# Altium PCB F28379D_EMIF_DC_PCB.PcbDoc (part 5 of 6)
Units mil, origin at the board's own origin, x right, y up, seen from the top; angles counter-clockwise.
Board outline 3000 x 1480 mil, 6 copper layers (Top Layer, Signal Layer 1, Signal Layer 2, Signal Layer 3, Signal Layer 4, Bottom Layer), stack 61.4 mil thick; 51 components, 68 nets, 414 pads, 205 vias.
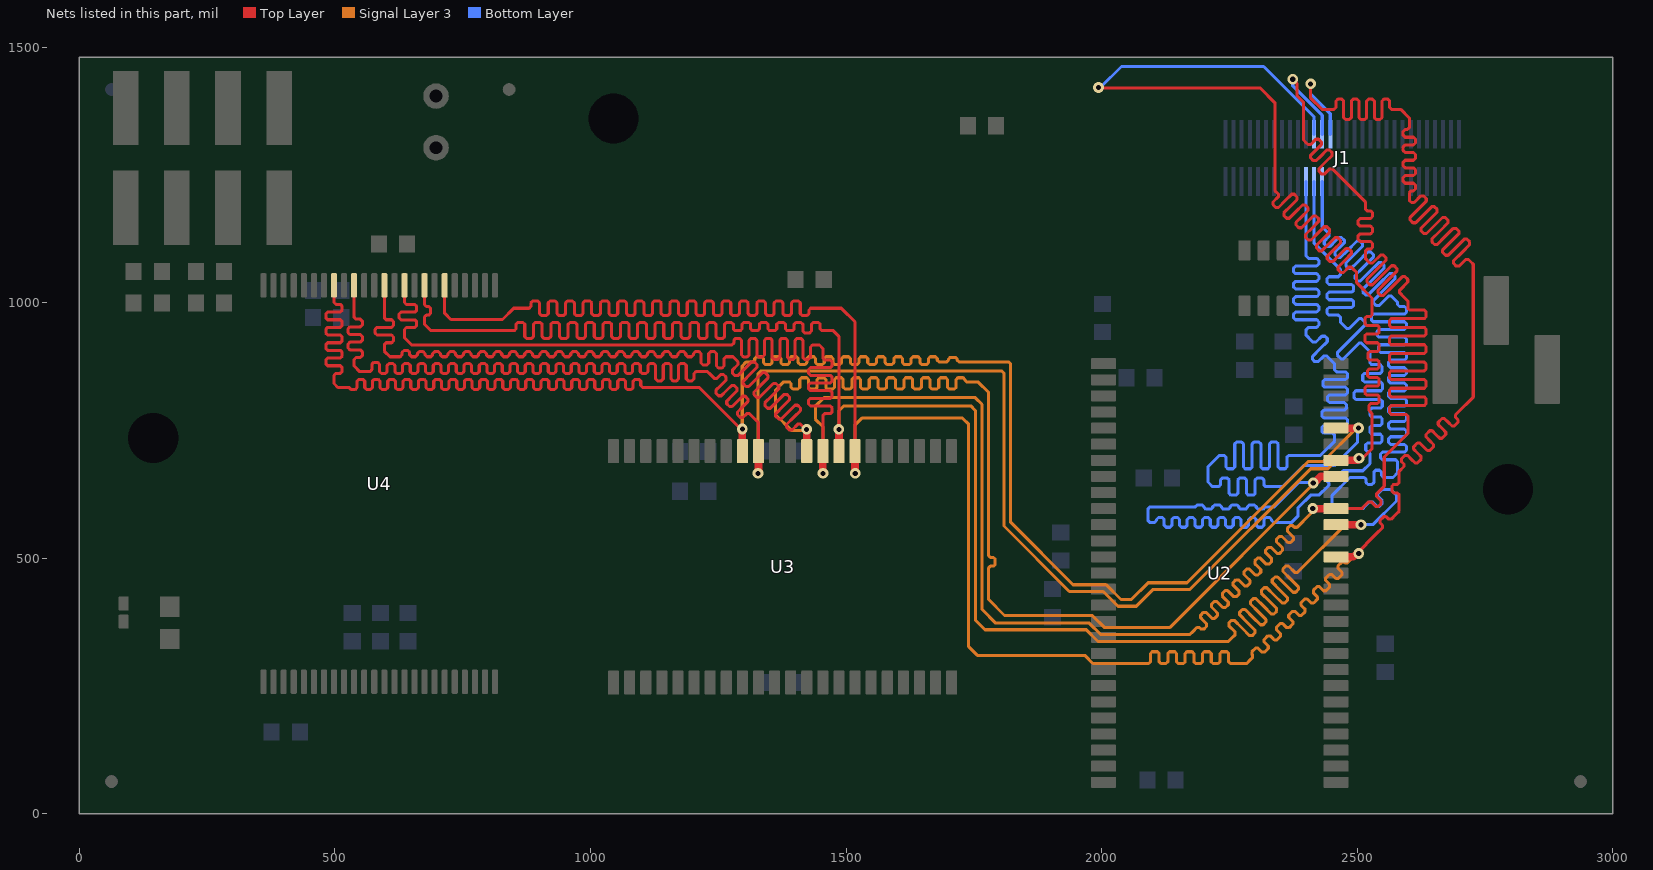
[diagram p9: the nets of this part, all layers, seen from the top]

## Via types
v1: diameter 21, hole 10, Top Layer to Bottom Layer, 204 vias
v2: diameter 20, hole 10, Top Layer to Bottom Layer, 1 vias

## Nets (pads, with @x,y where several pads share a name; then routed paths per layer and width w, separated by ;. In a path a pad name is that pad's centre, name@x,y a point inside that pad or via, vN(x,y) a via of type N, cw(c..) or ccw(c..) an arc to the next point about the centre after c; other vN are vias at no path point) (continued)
EM_D8: J1.34@2447.38,1329.26 U2.42 U3.29 U4.30 | length 6438.6
  Top Layer w6: U4.30@714.95,1033.8 714.95,979 726.95,967 828,967 850,989 875,989 880.1,989 883.5,992.4 883.5,999.59 886.9,1002.99 897.1,1002.99 900.5,999.59 900.5,989 900.5,978.41 903.9,975.01 914.1,975.01 917.5,978.41 917.5,989 917.5,999.59 920.9,1002.99 931.1,1002.99 934.5,999.59 934.5,989 934.5,978.41 937.9,975.01 948.1,975.01 951.5,978.41 951.5,989 951.5,999.59 954.9,1002.99 965.1,1002.99 968.5,999.59 968.5,989 968.5,978.41 971.9,975.01 982.1,975.01 985.5,978.41 985.5,989 985.5,999.59 988.9,1002.99 999.1,1002.99 1002.5,999.59 1002.5,989 1002.5,978.41 1005.9,975.01 1016.1,975.01 1019.5,978.41 1019.5,989 1019.5,999.59 1022.9,1002.99 1033.1,1002.99 1036.5,999.59 1036.5,989 1036.5,978.41 1039.9,975.01 1050.1,975.01 1053.5,978.41 1053.5,989 1053.5,999.59 1056.9,1002.99 1067.1,1002.99 1070.5,999.59 1070.5,989 1070.5,978.41 1073.9,975.01 1084.1,975.01 1087.5,978.41 1087.5,989 1087.5,999.59 1090.9,1002.99 1101.1,1002.99 1104.5,999.59 1104.5,989 1104.5,978.41 1107.9,975.01 1118.1,975.01 1121.5,978.41 1121.5,989 1121.5,999.59 1124.9,1002.99 1135.1,1002.99 1138.5,999.59 1138.5,989 1138.5,978.41 1141.9,975.01 1152.1,975.01 1155.5,978.41 1155.5,989 1155.5,999.59 1158.9,1002.99 1169.1,1002.99 1172.5,999.59 1172.5,989 1172.5,978.41 1175.9,975.01 1186.1,975.01 1189.5,978.41 1189.5,989 1189.5,999.59 1192.9,1002.99 1203.1,1002.99 1206.5,999.59 1206.5,989 1206.5,978.41 1209.9,975.01 1220.1,975.01 1223.5,978.41 1223.5,989 1223.5,999.59 1226.9,1002.99 1237.1,1002.99 1240.5,999.59 1240.5,989 1240.5,978.41 1243.9,975.01 1254.1,975.01 1257.5,978.41 1257.5,989 1257.5,999.59 1260.9,1002.99 1271.1,1002.99 1274.5,999.59 1274.5,989 1274.5,978.41 1277.9,975.01 1288.1,975.01 1291.5,978.41 1291.5,989 1291.5,999.59 1294.9,1002.99 1305.1,1002.99 1308.5,999.59 1308.5,989 1308.5,978.41 1311.9,975.01 1322.1,975.01 1325.5,978.41 1325.5,989 1325.5,999.59 1328.9,1002.99 1339.1,1002.99 1342.5,999.59 1342.5,989 1342.5,978.41 1345.9,975.01 1356.1,975.01 1359.5,978.41 1359.5,989 1359.5,999.59 1362.9,1002.99 1373.1,1002.99 1376.5,999.59 1376.5,989 1376.5,978.41 1379.9,975.01 1390.1,975.01 1393.5,978.41 1393.5,989 1393.5,999.59 1396.9,1002.99 1407.1,1002.99 1410.5,999.59 1410.5,989 1410.5,978.41 1413.9,975.01 1424.1,975.01 1427.5,978.41 1427.5,985.6 1430.9,989 1491,989 1517.73,962.27 U3.29@1517.73,709.38 ; v1(2409,1428) 2409,1400 2431,1378 2451,1378 2454.75,1378 2458.5,1381.75 2458.5,1394.25 2462.25,1398 2469.75,1398 2473.5,1394.25 2473.5,1378 2473.5,1361.75 2477.25,1358 2484.75,1358 2488.5,1361.75 2488.5,1378 2488.5,1394.25 2492.25,1398 2499.75,1398 2503.5,1394.25 2503.5,1378 2503.5,1361.75 2507.25,1358 2514.75,1358 2518.5,1361.75 2518.5,1378 2518.5,1394.25 2522.25,1398 2529.75,1398 2533.5,1394.25 2533.5,1378 2533.5,1361.75 2537.25,1358 2544.75,1358 2548.5,1361.75 2548.5,1378 2548.5,1394.25 2552.25,1398 2559.75,1398 2563.5,1394.25 2563.5,1381.75 2567.25,1378 2578.5,1378 2581,1378 2585,1378 2602,1361 2602,1353.5 2602,1342.25 2598.25,1338.5 2593.75,1338.5 2590,1334.75 2590,1327.25 2593.75,1323.5 2602,1323.5 2610.25,1323.5 2614,1319.75 2614,1312.25 2610.25,1308.5 2602,1308.5 2593.75,1308.5 2590,1304.75 2590,1297.25 2593.75,1293.5 2602,1293.5 2610.25,1293.5 2614,1289.75 2614,1282.25 2610.25,1278.5 2602,1278.5 2593.75,1278.5 2590,1274.75 2590,1267.25 2593.75,1263.5 2602,1263.5 2610.25,1263.5 2614,1259.75 2614,1252.25 2610.25,1248.5 2602,1248.5 2593.75,1248.5 2590,1244.75 2590,1237.25 2593.75,1233.5 2602,1233.5 2610.25,1233.5 2614,1229.75 2614,1222.25 2610.25,1218.5 2605.75,1218.5 2602,1214.75 2602,1203.5 2602,1200 2603.5,1198.5 2606.15,1195.85 2611.45,1195.85 2624.54,1208.93 2629.84,1208.93 2635.14,1203.63 2635.14,1198.32 2619.41,1182.59 2603.68,1166.86 2603.68,1161.55 2608.98,1156.25 2614.28,1156.25 2630.02,1171.98 2645.75,1187.72 2651.05,1187.72 2656.36,1182.41 2656.36,1177.11 2640.62,1161.38 2624.89,1145.64 2624.89,1140.34 2630.19,1135.04 2635.5,1135.04 2651.23,1150.77 2666.96,1166.5 2672.27,1166.5 2677.57,1161.2 2677.57,1155.9 2661.84,1140.16 2646.1,1124.43 2646.1,1119.13 2651.41,1113.82 2656.71,1113.82 2672.44,1129.56 2688.18,1145.29 2693.48,1145.29 2698.78,1139.99 2698.78,1134.68 2683.05,1118.95 2667.32,1103.22 2667.32,1097.91 2672.62,1092.61 2677.92,1092.61 2693.66,1108.34 2709.39,1124.08 2714.69,1124.08 2720,1118.77 2720,1113.47 2704.26,1097.74 2688.53,1082 2688.53,1076.7 2693.83,1071.4 2699.14,1071.4 2712.22,1084.48 2717.52,1084.48 2721.5,1080.5 2727,1075 2727,815 2696,784 2692.39,780.39 2692.39,775.59 2697.34,770.63 2697.34,765.83 2690.13,758.61 2685.32,758.61 2677.97,765.97 2670.61,773.32 2665.81,773.32 2658.59,766.11 2658.59,761.3 2665.95,753.95 2673.3,746.59 2673.3,741.78 2666.09,734.57 2661.28,734.57 2653.93,741.93 2646.57,749.28 2641.76,749.28 2634.55,742.07 2634.55,737.26 2641.91,729.91 2649.26,722.55 2649.26,717.74 2642.05,710.53 2637.24,710.53 2629.89,717.89 2622.53,725.24 2617.72,725.24 2610.51,718.03 2610.51,713.22 2617.86,705.86 2625.22,698.51 2625.22,693.7 2618.01,686.49 2613.2,686.49 2605.84,693.84 2598.49,701.2 2593.68,701.2 2586.47,693.99 2586.47,689.18 2591.42,684.23 2591.42,679.42 2582,670 2582,661.5 2582,647.9 2578.6,644.5 2571.6,644.5 2568.2,641.1 2568.2,630.9 2571.6,627.5 2578.6,627.5 2582,624.1 2582,592 2575.99,585.99 2566.37,576.37 2561.56,576.37 2556.61,581.32 2551.8,581.32 2544.59,574.11 2544.59,569.3 2549.54,564.35 2549.54,559.54 2537.5,547.5 v1@2498,508
  Top Layer w15: U3.29@1517.73,709.38 1517.73,670.27 v1@1518,670 ; U2.42@2459.86,501 U2.42@2458.36,502.5 2492.5,502.5 v1@2498,508
  Signal Layer 3 w6: v1@1518,674 1518,761 1531,774 1728,774 1740,762 1740,327 1757,310 1967,310 1983,294 2091,294 2092.1,294 2095.5,297.4 2095.5,313.6 2098.9,317 2109.1,317 2112.5,313.6 2112.5,297.4 2115.9,294 2126.1,294 2129.5,297.4 2129.5,313.6 2132.9,317 2143.1,317 2146.5,313.6 2146.5,297.4 2149.9,294 2160.1,294 2163.5,297.4 2163.5,313.6 2166.9,317 2177.1,317 2180.5,313.6 2180.5,297.4 2183.9,294 2194.1,294 2197.5,297.4 2197.5,313.6 2200.9,317 2211.1,317 2214.5,313.6 2214.5,297.4 2217.9,294 2228.1,294 2231.5,297.4 2231.5,313.6 2234.9,317 2245.1,317 2248.5,313.6 2248.5,297.4 2251.9,294 2265.5,294 2274,294 2284,294 2292,302 2295.61,305.61 2295.61,310.41 2294.05,311.97 2294.05,316.78 2301.26,323.99 2306.07,323.99 2310.03,320.03 2313.99,316.07 2318.8,316.07 2326.01,323.28 2326.01,328.09 2322.05,332.05 2318.09,336.01 2318.09,340.82 2325.3,348.03 2330.11,348.03 2334.07,344.07 2338.03,340.11 2342.84,340.11 2350.05,347.33 2350.05,352.13 2346.09,356.09 2342.13,360.05 2342.13,364.86 2349.35,372.07 2354.15,372.07 2358.11,368.11 2362.07,364.15 2366.88,364.15 2374.1,371.37 2374.1,376.18 2370.14,380.14 2366.18,384.1 2366.18,388.9 2373.39,396.12 2378.2,396.12 2382.16,392.16 2386.12,388.2 2390.92,388.2 2398.14,395.41 2398.14,400.22 2394.18,404.18 2390.22,408.14 2390.22,412.95 2397.43,420.16 2402.24,420.16 2406.2,416.2 2410.16,412.24 2414.97,412.24 2422.18,419.45 2422.18,424.26 2418.22,428.22 2414.26,432.18 2414.26,436.99 2421.47,444.2 2426.28,444.2 2430.24,440.24 2434.2,436.28 2439.01,436.28 2446.22,443.49 2446.22,448.3 2442.26,452.26 2438.3,456.22 2438.3,461.03 2445.51,468.24 2450.32,468.24 2454.28,464.28 2458.24,460.32 2463.05,460.32 2470.26,467.53 2470.26,472.34 2466.3,476.3 2462.34,480.26 2462.34,485.07 2469.55,492.28 2474.36,492.28 2475.92,490.73 2480.73,490.73 2486,496 v1@2498,508
  Bottom Layer w6: v1(2409,1428) 2409,1408 2447.38,1369.62 J1.34@2447.38,1329.26
  other v1: 2503,509 1518,666
EM_D9: J1.35@2431.63,1236.74 U2.44 U3.30 U4.32 | length 6522.4
  Top Layer w6: U4.32@675.58,1033.8 675.58,1001 675.58,995.9 678.98,992.5 683.84,992.5 687.24,989.1 687.24,978.9 683.84,975.5 678.98,975.5 675.58,972.1 675.58,961 675.58,957.42 688,945 829,945 851.1,945 854.5,948.4 854.5,957.6 857.9,961 868.1,961 871.5,957.6 871.5,945 871.5,933.4 874.9,930 885.1,930 888.5,933.4 888.5,945 888.5,957.6 891.9,961 902.1,961 905.5,957.6 905.5,945 905.5,933.4 908.9,930 919.1,930 922.5,933.4 922.5,945 922.5,957.6 925.9,961 936.1,961 939.5,957.6 939.5,945 939.5,933.4 942.9,930 953.1,930 956.5,933.4 956.5,945 956.5,957.6 959.9,961 970.1,961 973.5,957.6 973.5,945 973.5,933.4 976.9,930 987.1,930 990.5,933.4 990.5,945 990.5,957.6 993.9,961 1004.1,961 1007.5,957.6 1007.5,945 1007.5,933.4 1010.9,930 1021.1,930 1024.5,933.4 1024.5,945 1024.5,957.6 1027.9,961 1038.1,961 1041.5,957.6 1041.5,945 1041.5,933.4 1044.9,930 1055.1,930 1058.5,933.4 1058.5,945 1058.5,957.6 1061.9,961 1072.1,961 1075.5,957.6 1075.5,945 1075.5,933.4 1078.9,930 1089.1,930 1092.5,933.4 1092.5,945 1092.5,957.6 1095.9,961 1106.1,961 1109.5,957.6 1109.5,945 1109.5,933.4 1112.9,930 1123.1,930 1126.5,933.4 1126.5,945 1126.5,957.6 1129.9,961 1140.1,961 1143.5,957.6 1143.5,945 1143.5,933.4 1146.9,930 1157.1,930 1160.5,933.4 1160.5,945 1160.5,957.6 1163.9,961 1174.1,961 1177.5,957.6 1177.5,945 1177.5,933.4 1180.9,930 1191.1,930 1194.5,933.4 1194.5,945 1194.5,957.6 1197.9,961 1208.1,961 1211.5,957.6 1211.5,945 1211.5,933.4 1214.9,930 1225.1,930 1228.5,933.4 1228.5,945 1228.5,957.6 1231.9,961 1242.1,961 1245.5,957.6 1245.5,945 1245.5,933.4 1248.9,930 1259.1,930 1262.5,933.4 1262.5,945 1262.5,957.6 1265.9,961 1276.1,961 1279.5,957.6 1279.5,948.4 1282.9,945 1293.1,945 1296.5,948.4 1296.5,957.6 1299.9,961 1310.1,961 1313.5,957.6 1313.5,948.4 1316.9,945 1327.1,945 1330.5,948.4 1330.5,957.6 1333.9,961 1344.1,961 1347.5,957.6 1347.5,948.4 1350.9,945 1361.1,945 1364.5,948.4 1364.5,957.6 1367.9,961 1378.1,961 1381.5,957.6 1381.5,948.4 1384.9,945 1395.1,945 1398.5,948.4 1398.5,957.6 1401.9,961 1412.1,961 1415.5,957.6 1415.5,945 1415.5,944.26 1418.9,940.86 1429.1,940.86 1432.5,944.26 1432.5,945 1432.5,957.6 1435.9,961 1446.1,961 1449.5,957.6 1449.5,948.4 1452.9,945 1466.5,945 1475,945 1486,934 v1(1486,752) v1@1486,750
  Top Layer w15: v1@1486,745 1486.24,744.76 U3.30@1486.24,709.38 ; U2.44@2458.36,565.49 v1@2506.51,565.49
  Signal Layer 3 w6: v1@1486,745 v1(1486,752) 1486,788 1496,798 1744,798 1753,789 1753,379 1772,360 1970,360 1993,337 2248,337 2253.3,342.3 2261.26,350.26 2261.26,355.56 2248.95,367.87 2248.95,373.18 2254.25,378.48 2259.55,378.48 2274.52,363.52 2289.48,348.55 2294.78,348.55 2300.09,353.86 2300.09,359.16 2285.12,374.12 2270.16,389.09 2270.16,394.39 2275.46,399.69 2280.77,399.69 2295.73,384.73 2310.69,369.77 2316,369.77 2321.3,375.07 2321.3,380.37 2306.34,395.34 2291.37,410.3 2291.37,415.6 2296.67,420.91 2301.98,420.91 2316.94,405.94 2331.91,390.98 2337.21,390.98 2342.51,396.28 2342.51,401.58 2327.55,416.55 2312.58,431.51 2312.58,436.82 2317.89,442.12 2323.19,442.12 2338.16,427.16 2353.12,412.19 2358.42,412.19 2363.73,417.49 2363.73,422.8 2348.76,437.76 2333.8,452.73 2333.8,458.03 2339.1,463.33 2344.4,463.33 2359.37,448.37 2374.33,433.4 2379.64,433.4 2384.94,438.71 2384.94,444.01 2369.98,458.98 2355.01,473.94 2355.01,479.24 2360.31,484.55 2365.62,484.55 2377.93,472.23 2383.23,472.23 2385,474 2476.49,565.49 v1@2506.51,565.49
  Bottom Layer w6: J1.35@2431.63,1236.74 2431.63,1148 2436.93,1142.7 2444.89,1134.74 2444.89,1129.44 2435.57,1120.12 2435.57,1114.81 2440.87,1109.51 2446.17,1109.51 2458.15,1121.48 2464.18,1127.52 2469.48,1127.52 2474.79,1122.21 2474.79,1116.91 2468.75,1110.88 2456.78,1098.9 2456.78,1093.6 2462.08,1088.3 2467.39,1088.3 2479.36,1100.27 2499.7,1120.61 2505.01,1120.61 2510.31,1115.31 2510.31,1110.01 2489.97,1089.66 2477.82,1077.51 2477.82,1072.21 2483.12,1066.91 2488.42,1066.91 2500.57,1079.06 2520.92,1099.4 2526.22,1099.4 2531.52,1094.1 2531.52,1088.79 2511.18,1068.45 2495.58,1052.85 2495.58,1047.55 2500.89,1042.25 2506.19,1042.25 2521.79,1057.84 2542.13,1078.19 2547.43,1078.19 2552.74,1072.88 2552.74,1067.58 2532.39,1047.24 2511,1025.85 2511,1020.54 2516.31,1015.24 2521.61,1015.24 2543,1036.63 2563.34,1056.97 2568.64,1056.97 2573.95,1051.67 2573.95,1046.37 2553.61,1026.02 2532.22,1004.63 2532.22,999.33 2537.52,994.03 2542.82,994.03 2561.56,1012.77 2566.86,1012.77 2574.82,1004.81 2579,1000.63 2579,1000 2579,996.25 2582.75,992.5 2592.63,992.5 2596.38,988.75 2596.38,981.25 2592.63,977.5 2579,977.5 2531.37,977.5 2527.62,973.75 2527.62,966.25 2531.37,962.5 2579,962.5 2592.63,962.5 2596.38,958.75 2596.38,951.25 2592.63,947.5 2579,947.5 2542.56,947.5 2538.81,943.75 2538.81,936.25 2542.56,932.5 2579,932.5 2592.63,932.5 2596.38,928.75 2596.38,921.25 2592.63,917.5 2579,917.5 2545.5,917.5 2541.75,913.75 2541.75,906.25 2545.5,902.5 2579,902.5 2592.63,902.5 2596.38,898.75 2596.38,891.25 2592.63,887.5 2579,887.5 2565.37,887.5 2561.62,883.75 2561.62,876.25 2565.37,872.5 2579,872.5 2592.63,872.5 2596.38,868.75 2596.38,861.25 2592.63,857.5 2579,857.5 2565.37,857.5 2561.62,853.75 2561.62,846.25 2565.37,842.5 2579,842.5 2592.63,842.5 2596.38,838.75 2596.38,831.25 2592.63,827.5 2579,827.5 2565.37,827.5 2561.62,823.75 2561.62,816.25 2565.37,812.5 2579,812.5 2592.63,812.5 2596.38,808.75 2596.38,801.25 2592.63,797.5 2579,797.5 2565.37,797.5 2561.62,793.75 2561.62,786.25 2565.37,782.5 2579,782.5 2592.63,782.5 2596.38,778.75 2596.38,771.25 2592.63,767.5 2579,767.5 2565.37,767.5 2561.62,763.75 2561.62,756.25 2565.37,752.5 2579,752.5 2592.63,752.5 2596.38,748.75 2596.38,741.25 2592.63,737.5 2579,737.5 2565.37,737.5 2561.62,733.75 2561.62,726.25 2565.37,722.5 2579,722.5 2592.63,722.5 2596.38,718.75 2596.38,711.25 2592.63,707.5 2579,707.5 2549.37,707.5 2545.62,703.75 2545.62,696.25 2549.37,692.5 2575.25,692.5 2579,688.75 2579,677.5 2579,667 2570,658 2562.5,658 2551.25,658 2547.5,661.75 2547.5,668.25 2543.75,672 2536.25,672 2532.5,668.25 2532.5,658 2532.5,647.75 2528.75,644 2521.25,644 2517.5,647.75 2517.5,654.25 2513.75,658 2504,658 2486,658 2451,623 2451,602 2456,597 2511,597 2516.3,602.3 2524.26,610.26 2529.56,610.26 2538.3,601.52 2543.61,601.52 2548.91,606.82 2548.91,612.12 2540.17,620.86 2540.17,626.17 2548,634 2566,634 2577,623 2577,612 2530.49,565.49 v1(2507.51,565.49) v1@2506.51,565.49
EM_D10: J1.36@2431.63,1329.26 U2.45 U3.31 U4.34 | length 6440.2
  Top Layer w6: U4.34@636.21,1033.8 636.21,1026.3 636.21,1011.3 636.21,1000.05 639.96,996.3 656.46,996.3 660.21,992.55 660.21,985.05 656.46,981.3 636.21,981.3 629.35,981.3 625.6,977.55 625.6,970.05 629.35,966.3 636.21,966.3 656.46,966.3 660.21,962.55 660.21,955.05 656.46,951.3 639.96,951.3 636.21,947.55 636.21,936.3 636.21,931 650.21,917 1273,917 1276.75,917 1280.5,920.75 1280.5,926.25 1284.25,930 1291.75,930 1295.5,926.25 1295.5,917 1295.5,897.59 1299.25,893.84 1306.75,893.84 1310.5,897.59 1310.5,917 1310.5,926.25 1314.25,930 1321.75,930 1325.5,926.25 1325.5,917 1325.5,897.6 1329.25,893.85 1336.75,893.85 1340.5,897.6 1340.5,917 1340.5,926.25 1344.25,930 1351.75,930 1355.5,926.25 1355.5,917 1355.5,892.75 1359.25,889 1366.75,889 1370.5,892.75 1370.5,917 1370.5,926.25 1374.25,930 1381.75,930 1385.5,926.25 1385.5,917 1385.5,892.75 1389.25,889 1396.75,889 1400.5,892.75 1400.5,917 1400.5,926.25 1404.25,930 1411.75,930 1415.5,926.25 1415.5,917 1415.5,892.75 1419.25,889 1426.75,889 1430.5,892.75 1430.5,913.25 1434.25,917 1445.5,917 1448,917 1454.74,910.26 1454.74,902.76 1454.74,891.51 1458.49,887.76 1469.25,887.76 1473,884.01 1473,876.51 1469.25,872.76 1454.74,872.76 1430.49,872.76 1426.74,869.01 1426.74,861.51 1430.49,857.76 1454.74,857.76 1469.25,857.76 1473,854.01 1473,846.51 1469.25,842.76 1454.74,842.76 1430.49,842.76 1426.74,839.01 1426.74,831.51 1430.49,827.76 1454.74,827.76 1469.25,827.76 1473,824.01 1473,816.51 1469.25,812.76 1454.74,812.76 1430.49,812.76 1426.74,809.01 1426.74,801.51 1430.49,797.76 1454.74,797.76 1469.25,797.76 1473,794.01 1473,786.51 1469.25,782.76 1458.49,782.76 1454.74,779.01 1454.74,754 U3.31@1454.74,709.38 ; v1(2374,1437) 2382,1429 2382,1405 2395,1392 2395,1318 2401,1312 2403.65,1309.35 2408.95,1309.35 2419.21,1319.6 2424.51,1319.6 2429.81,1314.3 2429.81,1308.99 2416.91,1296.09 2409,1288.18 2409,1282.88 2414.3,1277.57 2419.6,1277.57 2427.52,1285.48 2440.42,1298.39 2445.72,1298.39 2451.03,1293.08 2451.03,1287.78 2438.12,1274.88 2425.22,1261.97 2425.22,1256.67 2430.52,1251.37 2435.82,1251.37 2446.08,1261.62 2451.38,1261.62 2495,1218 2516,1197 2516,1187 2516,1183.25 2519.75,1179.5 2526.25,1179.5 2530,1175.75 2530,1168.25 2526.25,1164.5 2516,1164.5 2505.75,1164.5 2502,1160.75 2502,1153.25 2505.75,1149.5 2516,1149.5 2526.25,1149.5 2530,1145.75 2530,1138.25 2526.25,1134.5 2516,1134.5 2505.75,1134.5 2502,1130.75 2502,1123.25 2505.75,1119.5 2516,1119.5 2526.25,1119.5 2530,1115.75 2530,1108.25 2526.25,1104.5 2519.75,1104.5 2516,1100.75 2516,1089.5 2516,1086 2516.5,1085.5 2522,1080 2524.65,1077.35 2529.95,1077.35 2545.86,1093.26 2551.17,1093.26 2556.47,1087.95 2556.47,1082.65 2537.91,1064.09 2519.35,1045.53 2519.35,1040.23 2524.65,1034.92 2529.95,1034.92 2548.52,1053.48 2567.08,1072.05 2572.38,1072.05 2577.68,1066.74 2577.68,1061.44 2559.12,1042.88 2540.56,1024.32 2540.56,1019.01 2545.86,1013.71 2551.17,1013.71 2569.73,1032.27 2588.29,1050.83 2593.59,1050.83 2598.9,1045.53 2598.9,1040.23 2582.99,1024.32 2582.99,1019.01 2590.94,1011.06 2593.5,1008.5 2599,1003 2599,994 2599,988.9 2602.4,985.5 2631.35,985.5 2634.75,982.1 2634.75,971.9 2631.35,968.5 2599,968.5 2566.65,968.5 2563.25,965.1 2563.25,954.9 2566.65,951.5 2599,951.5 2631.35,951.5 2634.75,948.1 2634.75,937.9 2631.35,934.5 2599,934.5 2566.65,934.5 2563.25,931.1 2563.25,920.9 2566.65,917.5 2599,917.5 2631.35,917.5 2634.75,914.1 2634.75,903.9 2631.35,900.5 2599,900.5 2566.65,900.5 2563.25,897.1 2563.25,886.9 2566.65,883.5 2599,883.5 2631.35,883.5 2634.75,880.1 2634.75,869.9 2631.35,866.5 2599,866.5 2566.65,866.5 2563.25,863.1 2563.25,852.9 2566.65,849.5 2599,849.5 2631.35,849.5 2634.75,846.1 2634.75,835.9 2631.35,832.5 2599,832.5 2566.65,832.5 2563.25,829.1 2563.25,818.9 2566.65,815.5 2599,815.5 2631.35,815.5 2634.75,812.1 2634.75,801.9 2631.35,798.5 2599,798.5 2566.65,798.5 2563.25,795.1 2563.25,784.9 2566.65,781.5 2595.6,781.5 2599,778.1 2599,744 2553,698 2553,643 2553,641 2538.15,626.15 2538.15,620.85 2546.99,612.01 2546.99,606.71 2541.69,601.4 2536.38,601.4 2527.55,610.24 2522.24,610.24 2514.29,602.29 2508.98,596.98 U2.45@2458.36,596.98
  Top Layer w15: U3.31@1454.74,709.38 1454.74,670.26 v1@1455,670 ; v1@2419.02,596.98 U2.45@2458.36,596.98
  Signal Layer 3 w6: v1@1455,674 1455,757 1440,772 1440,797 1457,814 1753,814 1766,801 1766,400 1793,373 1976,373 1998,351 2173,351 2178.3,356.3 2186.26,364.26 2191.56,364.26 2194.74,361.08 2200.05,361.08 2205.35,366.38 2205.35,371.68 2199.52,377.52 2193.68,383.35 2193.68,388.65 2198.99,393.96 2204.29,393.96 2210.12,388.12 2215.96,382.29 2221.26,382.29 2226.56,387.59 2226.56,392.9 2220.73,398.73 2214.9,404.56 2214.9,409.87 2220.2,415.17 2225.5,415.17 2231.34,409.34 2237.17,403.5 2242.47,403.5 2247.78,408.81 2247.78,414.11 2241.94,419.94 2236.11,425.78 2236.11,431.08 2241.41,436.38 2246.72,436.38 2252.55,430.55 2258.38,424.72 2263.69,424.72 2268.99,430.02 2268.99,435.32 2263.16,441.16 2257.32,446.99 2257.32,452.29 2262.63,457.6 2267.93,457.6 2273.76,451.76 2279.6,445.93 2284.9,445.93 2290.2,451.23 2290.2,456.54 2284.37,462.37 2278.54,468.2 2278.54,473.51 2283.84,478.81 2289.14,478.81 2294.98,472.98 2300.81,467.14 2306.11,467.14 2311.42,472.45 2311.42,477.75 2305.58,483.58 2299.75,489.42 2299.75,494.72 2305.05,500.02 2310.36,500.02 2316.19,494.19 2322.02,488.36 2327.33,488.36 2332.63,493.66 2332.63,498.96 2326.8,504.8 2320.96,510.63 2320.96,515.93 2326.27,521.24 2331.57,521.24 2337.4,515.4 2343.24,509.57 2348.54,509.57 2353.84,514.87 2353.84,520.18 2348.01,526.01 2342.18,531.84 2342.18,537.15 2347.48,542.45 2352.78,542.45 2358.62,536.62 2364.45,530.78 2369.75,530.78 2375.06,536.09 2375.06,541.39 2369.22,547.22 2363.39,553.06 2363.39,558.36 2368.69,563.66 2374,563.66 2377.18,560.48 2382.48,560.48 2406.5,584.5 v1@2419,597
  Bottom Layer w6: v1(2374,1437) 2374,1424 2431.63,1366.37 J1.36@2431.63,1329.26
  other v1: 2413,597 1455,666
EM_D11: J1.37@2415.88,1236.74 U2.47 U3.32 U4.36 | length 6500.2
  Top Layer w6: U4.36@596.84,1033.8 596.84,974 596.84,970.25 600.59,966.5 611.09,966.5 614.84,962.75 614.84,955.25 611.09,951.5 596.84,951.5 582.59,951.5 578.84,947.75 578.84,940.25 582.59,936.5 596.84,936.5 611.09,936.5 614.84,932.75 614.84,925.25 611.09,921.5 600.59,921.5 596.84,917.75 596.84,907 596.84,905 607.84,894 624,894 627.75,894 631.5,897.75 631.5,902.61 635.25,906.36 642.75,906.36 646.5,902.61 646.5,897.75 650.25,894 657.75,894 661.5,897.75 661.5,900.25 665.25,904 672.75,904 676.5,900.25 676.5,897.75 680.25,894 687.75,894 691.5,897.75 691.5,900.25 695.25,904 702.75,904 706.5,900.25 706.5,897.75 710.25,894 717.75,894 721.5,897.75 721.5,900.25 725.25,904 732.75,904 736.5,900.25 736.5,897.75 740.25,894 747.75,894 751.5,897.75 751.5,900.25 755.25,904 762.75,904 766.5,900.25 766.5,897.75 770.25,894 777.75,894 781.5,897.75 781.5,900.25 785.25,904 792.75,904 796.5,900.25 796.5,897.75 800.25,894 807.75,894 811.5,897.75 811.5,900.25 815.25,904 822.75,904 826.5,900.25 826.5,897.75 830.25,894 837.75,894 841.5,897.75 841.5,900.25 845.25,904 852.75,904 856.5,900.25 856.5,897.75 860.25,894 867.75,894 871.5,897.75 871.5,900.25 875.25,904 882.75,904 886.5,900.25 886.5,897.75 890.25,894 897.75,894 901.5,897.75 901.5,900.25 905.25,904 912.75,904 916.5,900.25 916.5,897.75 920.25,894 927.75,894 931.5,897.75 931.5,900.25 935.25,904 942.75,904 946.5,900.25 946.5,897.75 950.25,894 957.75,894 961.5,897.75 961.5,900.25 965.25,904 972.75,904 976.5,900.25 976.5,897.75 980.25,894 987.75,894 991.5,897.75 991.5,900.25 995.25,904 1002.75,904 1006.5,900.25 1006.5,897.75 1010.25,894 1017.75,894 1021.5,897.75 1021.5,900.25 1025.25,904 1032.75,904 1036.5,900.25 1036.5,897.75 1040.25,894 1047.75,894 1051.5,897.75 1051.5,900.25 1055.25,904 1062.75,904 1066.5,900.25 1066.5,897.75 1070.25,894 1077.75,894 1081.5,897.75 1081.5,900.25 1085.25,904 1092.75,904 1096.5,900.25 1096.5,897.75 1100.25,894 1107.75,894 1111.5,897.75 1111.5,900.25 1115.25,904 1122.75,904 1126.5,900.25 1126.5,897.75 1130.25,894 1137.75,894 1141.5,897.75 1141.5,900.25 1145.25,904 1152.75,904 1156.5,900.25 1156.5,897.75 1160.25,894 1167.75,894 1171.5,897.75 1171.5,900.25 1175.25,904 1182.75,904 1186.5,900.25 1186.5,897.75 1190.25,894 1197.75,894 1201.5,897.75 1201.5,900.25 1205.25,904 1212.75,904 1216.5,900.25 1216.5,894 1216.5,881.75 1220.25,878 1227.75,878 1231.5,881.75 1231.5,894 1231.5,900.25 1235.25,904 1242.75,904 1246.5,900.25 1246.5,894 1246.5,875.91 1250.25,872.16 1257.75,872.16 1261.5,875.91 1261.5,890.25 1265.25,894 1270,894 1279,894 1280,893 1288.87,884.13 1288.87,878.82 1277.64,867.59 1277.64,862.29 1282.94,856.98 1288.24,856.98 1302.13,870.87 1315.36,884.09 1320.66,884.09 1325.96,878.79 1325.96,873.49 1312.74,860.26 1298.85,846.38 1298.85,841.07 1304.15,835.77 1309.46,835.77 1323.34,849.66 1336.57,862.88 1341.87,862.88 1347.18,857.58 1347.18,852.27 1333.95,839.05 1320.06,825.16 1320.06,819.86 1325.37,814.56 1330.67,814.56 1344.56,828.44 1357.78,841.67 1363.09,841.67 1368.39,836.36 1368.39,831.06 1355.16,817.84 1341.28,803.95 1341.28,798.65 1346.58,793.34 1351.88,793.34 1365.77,807.23 1379,820.45 1384.3,820.45 1389.6,815.15 1389.6,809.85 1376.38,796.62 1362.49,782.74 1362.49,777.43 1367.79,772.13 1373.1,772.13 1386.98,786.02 1400.21,799.24 1405.51,799.24 1410.82,793.94 1410.82,788.64 1397.59,775.41 1383.7,761.52 1383.7,756.22 1389.01,750.92 1394.31,750.92 1405.55,762.15 1410.85,762.15 1413.5,759.5 v1@1423,750
  Top Layer w15: v1@1423,745 1423.24,744.76 U3.32@1423.24,709.38 ; v1@2417.02,647.98 2429.02,659.98 U2.47@2458.36,659.98
  Signal Layer 3 w6: v1@1423,745 1423,750 1393,750 1362,781 1362,829 1378,845 1389.1,845 1392.5,841.6 1392.5,834.4 1395.9,831 1406.1,831 1409.5,834.4 1409.5,845 1409.5,849.6 1412.9,853 1423.1,853 1426.5,849.6 1426.5,845 1426.5,834.4 1429.9,831 1440.1,831 1443.5,834.4 1443.5,845 1443.5,849.6 1446.9,853 1457.1,853 1460.5,849.6 1460.5,845 1460.5,834.4 1463.9,831 1474.1,831 1477.5,834.4 1477.5,845 1477.5,849.6 1480.9,853 1491.1,853 1494.5,849.6 1494.5,845 1494.5,834.4 1497.9,831 1508.1,831 1511.5,834.4 1511.5,845 1511.5,849.6 1514.9,853 1525.1,853 1528.5,849.6 1528.5,845 1528.5,834.4 1531.9,831 1542.1,831 1545.5,834.4 1545.5,845 1545.5,849.6 1548.9,853 1559.1,853 1562.5,849.6 1562.5,845 1562.5,834.4 1565.9,831 1576.1,831 1579.5,834.4 1579.5,845 1579.5,849.6 1582.9,853 1593.1,853 1596.5,849.6 1596.5,845 1596.5,834.4 1599.9,831 1610.1,831 1613.5,834.4 1613.5,845 1613.5,849.6 1616.9,853 1627.1,853 1630.5,849.6 1630.5,845 1630.5,834.4 1633.9,831 1644.1,831 1647.5,834.4 1647.5,845 1647.5,849.6 1650.9,853 1661.1,853 1664.5,849.6 1664.5,845 1664.5,834.4 1667.9,831 1678.1,831 1681.5,834.4 1681.5,845 1681.5,849.6 1684.9,853 1695.1,853 1698.5,849.6 1698.5,845 1698.5,834.4 1701.9,831 1712.1,831 1715.5,834.4 1715.5,845 1715.5,849.6 1718.9,853 1729.1,853 1732.5,849.6 1732.5,848.4 1735.9,845 1749.5,845 1758,845 1779,824 1779,510 1779,504.9 1782.4,501.5 1788.4,501.5 1791.8,498.1 1791.8,487.9 1788.4,484.5 1782.4,484.5 1779,481.1 1779,473 1779,419 1810,388 1982,388 2006,364 2133.05,364 v1@2417.02,647.98
  Bottom Layer w6: J1.37@2415.88,1236.74 2415.88,1116.12 2467,1065 2467,1054.25 2463.25,1050.5 2444.75,1050.5 2441,1046.75 2441,1039.25 2444.75,1035.5 2467,1035.5 2489.25,1035.5 2493,1031.75 2493,1024.25 2489.25,1020.5 2467,1020.5 2444.75,1020.5 2441,1016.75 2441,1009.25 2444.75,1005.5 2467,1005.5 2489.25,1005.5 2493,1001.75 2493,994.25 2489.25,990.5 2467,990.5 2444.75,990.5 2441,986.75 2441,979.25 2444.75,975.5 2463.25,975.5 2467,971.75 2467,962 2476,953 2479.61,949.39 2484.41,949.39 2503.57,968.55 2508.38,968.55 2515.59,961.34 2515.59,956.53 2494.03,934.97 2461.08,902.02 2461.08,897.21 2468.29,890 2473.1,890 2504.1,921 2508,921 2525,904 2525,887 2525,881.9 2528.4,878.5 2545.27,878.5 2548.67,875.1 2548.67,864.9 2545.27,861.5 2525,861.5 2514.35,861.5 2510.95,858.1 2510.95,847.9 2514.35,844.5 2525,844.5 2546.29,844.5 2549.69,841.1 2549.69,830.9 2546.29,827.5 2525,827.5 2497.47,827.5 2494.07,824.1 2494.07,813.9 2497.47,810.5 2525,810.5 2545.61,810.5 2549.01,807.1 2549.01,796.9 2545.61,793.5 2528.4,793.5 2525,790.1 2525,779.9 2528.4,776.5 2545.22,776.5 2548.62,773.1 2548.62,762.9 2545.22,759.5 2528.4,759.5 2525,756.1 2525,745.9 2528.4,742.5 2545.22,742.5 2548.62,739.1 2548.62,728.9 2545.22,725.5 2525,725.5 2520.2,725.5 2516.8,722.1 2516.8,711.9 2520.2,708.5 2521.6,708.5 2525,705.1 2525,704 2525,685 2511,671 2473,671 2466.5,664.5 2461.44,659.44 2456.63,659.44 2448.06,668 2443.25,668 2436.04,660.79 2436.04,655.98 2444.61,647.41 2444.61,642.61 2441,639 2426,624 2410,624 2384,598 2384,582 2372,570 2350,570 2336.25,570 2332.5,573.75 2332.5,575.75 2328.75,579.5 2321.25,579.5 2317.5,575.75 2317.5,570 2317.5,564.25 2313.75,560.5 2306.25,560.5 2302.5,564.25 2302.5,570 2302.5,575.75 2298.75,579.5 2291.25,579.5 2287.5,575.75 2287.5,570 2287.5,564.25 2283.75,560.5 2276.25,560.5 2272.5,564.25 2272.5,570 2272.5,575.75 2268.75,579.5 2261.25,579.5 2257.5,575.75 2257.5,570 2257.5,564.25 2253.75,560.5 2246.25,560.5 2242.5,564.25 2242.5,570 2242.5,575.75 2238.75,579.5 2231.25,579.5 2227.5,575.75 2227.5,570 2227.5,564.25 2223.75,560.5 2216.25,560.5 2212.5,564.25 2212.5,570 2212.5,575.75 2208.75,579.5 2201.25,579.5 2197.5,575.75 2197.5,570 2197.5,564.25 2193.75,560.5 2186.25,560.5 2182.5,564.25 2182.5,570 2182.5,575.75 2178.75,579.5 2171.25,579.5 2167.5,575.75 2167.5,570 2167.5,564.25 2163.75,560.5 2156.25,560.5 2152.5,564.25 2152.5,570 2152.5,575.75 2148.75,579.5 2141.25,579.5 2137.5,575.75 2137.5,570 2137.5,564.25 2133.75,560.5 2126.25,560.5 2122.5,564.25 2122.5,570 2122.5,575.75 2118.75,579.5 2111.25,579.5 2107.5,575.75 2107.5,573.75 2103.75,570 2100,570 2094,570 2091,573 2091,597 2094,600 2175,600 2182.9,600 2183.5,600.6 2186.9,604 2197.1,604 2200.5,600.6 2200.5,600 2200.5,599.4 2203.9,596 2214.1,596 2217.5,599.4 2217.5,600 2217.5,600.6 2220.9,604 2231.1,604 2234.5,600.6 2234.5,600 2234.5,599.4 2237.9,596 2248.1,596 2251.5,599.4 2251.5,600 2251.5,600.6 2254.9,604 2265.1,604 2268.5,600.6 2268.5,600 2268.5,599.4 2271.9,596 2282.1,596 2285.5,599.4 2285.5,600 2285.5,600.6 2288.9,604 2299.1,604 2302.5,600.6 2302.5,600 2302.5,599.4 2305.9,596 2316.1,596 2319.5,599.4 2320.1,600 2333,600 2338,600 2385.98,647.98 v1@2417.02,647.98
  other v1: 2414.02,646.98 1423,752
EM_D12: J1.38@2415.88,1329.26 U2.48 U3.35 U4.39 | length 6413.3
  Top Layer w6: U4.39@537.79,1033.8 537.79,975 537.79,971.25 541.54,967.5 550.04,967.5 553.79,963.75 553.79,956.25 550.04,952.5 537.79,952.5 529.38,952.5 525.63,948.75 525.63,941.25 529.38,937.5 537.79,937.5 550.04,937.5 553.79,933.75 553.79,926.25 550.04,922.5 537.79,922.5 529.38,922.5 525.63,918.75 525.63,911.25 529.38,907.5 537.79,907.5 550.04,907.5 553.79,903.75 553.79,896.25 550.04,892.5 541.54,892.5 537.79,888.75 537.79,886 537.79,876 548.79,865 565,865 568.75,865 572.5,868.75 572.5,879.25 576.25,883 583.75,883 587.5,879.25 587.5,865 ; 587.5,864.96 591.25,861.21 598.75,861.21 602.5,864.96 ; 602.5,865 602.5,877.25 606.25,881 613.75,881 617.5,877.25 617.5,865 ; 617.5,864.96 621.25,861.21 628.75,861.21 632.5,864.96 ; 632.5,865 632.5,877.25 636.25,881 643.75,881 647.5,877.25 647.5,865 ; 647.5,864.96 651.25,861.21 658.75,861.21 662.5,864.96 ; 662.5,865 662.5,877.25 666.25,881 673.75,881 677.5,877.25 677.5,865 ; 677.5,864.96 681.25,861.21 688.75,861.21 692.5,864.96 ; 692.5,865 692.5,877.25 696.25,881 703.75,881 707.5,877.25 707.5,865 ; 707.5,864.96 711.25,861.21 718.75,861.21 722.5,864.96 ; 722.5,865 722.5,877.25 726.25,881 733.75,881 737.5,877.25 737.5,865 ; 737.5,864.96 741.25,861.21 748.75,861.21 752.5,864.96 ; 752.5,865 752.5,877.25 756.25,881 763.75,881 767.5,877.25 767.5,865 ; 767.5,864.96 771.25,861.21 778.75,861.21 782.5,864.96 ; 782.5,865 782.5,877.25 786.25,881 793.75,881 797.5,877.25 797.5,865 ; 797.5,864.96 801.25,861.21 808.75,861.21 812.5,864.96 ; 812.5,865 812.5,877.25 816.25,881 823.75,881 827.5,877.25 827.5,865 ; 827.5,864.96 831.25,861.21 838.75,861.21 842.5,864.96 ; 842.5,865 842.5,877.25 846.25,881 853.75,881 857.5,877.25 857.5,865 ; 857.5,864.96 861.25,861.21 868.75,861.21 872.5,864.96 ; 872.5,865 872.5,877.25 876.25,881 883.75,881 887.5,877.25 887.5,865 ; 887.5,864.96 891.25,861.21 898.75,861.21 902.5,864.96 ; 902.5,865 902.5,877.25 906.25,881 913.75,881 917.5,877.25 917.5,865 ; 917.5,864.96 921.25,861.21 928.75,861.21 932.5,864.96 ; 932.5,865 932.5,877.25 936.25,881 943.75,881 947.5,877.25 947.5,865 ; 947.5,864.96 951.25,861.21 958.75,861.21 962.5,864.96 ; 962.5,865 962.5,877.25 966.25,881 973.75,881 977.5,877.25 977.5,865 ; 977.5,864.96 981.25,861.21 988.75,861.21 992.5,864.96 ; 992.5,865 992.5,877.25 996.25,881 1003.75,881 1007.5,877.25 1007.5,865 ; 1007.5,864.96 1011.25,861.21 1018.75,861.21 1022.5,864.96 ; 1022.5,865 1022.5,877.25 1026.25,881 1033.75,881 1037.5,877.25 1037.5,865 ; 1037.5,864.96 1041.25,861.21 1048.75,861.21 1052.5,864.96 ; 1052.5,865 1052.5,877.25 1056.25,881 1063.75,881 1067.5,877.25 1067.5,865 ; 1067.5,864.96 1071.25,861.21 1078.75,861.21 1082.5,864.96 ; 1082.5,865 1082.5,877.25 1086.25,881 1093.75,881 1097.5,877.25 1097.5,865 ; 1097.5,864.96 1101.25,861.21 1108.75,861.21 1112.5,864.96 ; 1112.5,865 1112.5,877.25 1116.25,881 1123.75,881 1127.5,877.25 1127.5,865 1127.5,850.75 1131.25,847 1138.75,847 1142.5,850.75 1142.5,865 1142.5,877.25 1146.25,881 1153.75,881 1157.5,877.25 1157.5,865 1157.5,850.75 1161.25,847 1168.75,847 1172.5,850.75 1172.5,865 1172.5,877.25 1176.25,881 1183.75,881 1187.5,877.25 1187.5,865 1187.5,850.75 1191.25,847 1198.75,847 1202.5,850.75 1202.5,861.25 1206.25,865 1217.5,865 1229,865 1234.3,859.7 1242.26,851.74 1247.56,851.74 1254.99,859.17 1260.29,859.17 1265.59,853.86 1265.59,848.56 1255.52,838.48 1245.44,828.41 1245.44,823.1 1250.74,817.8 1256.05,817.8 1266.12,827.88 1276.2,837.95 1281.5,837.95 1286.81,832.65 1286.81,827.35 1276.73,817.27 1266.65,807.19 1266.65,801.89 1271.96,796.59 1277.26,796.59 1287.34,806.66 1297.41,816.74 1302.72,816.74 1308.02,811.44 1308.02,806.13 1297.94,796.06 1287.87,785.98 1287.87,780.68 1293.17,775.37 1298.47,775.37 1305.9,782.8 1311.2,782.8 1328.76,765.24 1328.76,757.74 1328.76,753 U3.35@1328.76,709.38 ; v1@1994,1420 2310,1420 2339,1391 2339,1219 2344,1214 2345.66,1212.34 2345.66,1207.04 2335.41,1196.78 2335.41,1191.48 2340.71,1186.18 2346.01,1186.18 2358.92,1199.08 2371.82,1211.99 2377.13,1211.99 2382.43,1206.68 2382.43,1201.38 2369.52,1188.48 2356.62,1175.57 2356.62,1170.27 2361.92,1164.96 2367.23,1164.96 2380.13,1177.87 2393.04,1190.77 2398.34,1190.77 2403.64,1185.47 2403.64,1180.17 2390.74,1167.26 2380.48,1157.01 2380.48,1151.71 2385.79,1146.4 2391.09,1146.4 2401.34,1156.66 2414.25,1169.56 2419.55,1169.56 2424.86,1164.26 2424.86,1158.95 2411.95,1146.05 2399.05,1133.14 2399.05,1127.84 2404.35,1122.54 2409.65,1122.54 2422.56,1135.44 2435.46,1148.35 2440.77,1148.35 2446.07,1143.04 2446.07,1137.74 2433.16,1124.84 2420.26,1111.93 2420.26,1106.63 2425.56,1101.32 2430.87,1101.32 2443.77,1114.23 2456.68,1127.13 2461.98,1127.13 2467.28,1121.83 2467.28,1116.53 2454.38,1103.62 2441.47,1090.72 2441.47,1085.42 2446.78,1080.11 2452.08,1080.11 2464.98,1093.02 2477.89,1105.92 2483.19,1105.92 2488.49,1100.62 2488.49,1095.31 2475.59,1082.41 2462.69,1069.51 2462.69,1064.2 2467.99,1058.9 2473.29,1058.9 2483.55,1069.15 2488.85,1069.15 2491.5,1066.5 2499,1059 2499,1039 2529,1009 2529,983 2529,975.9 2525.6,972.5 2518.4,972.5 2515,969.1 2515,958.9 2518.4,955.5 2529,955.5 2539.6,955.5 2543,952.1 2543,941.9 2539.6,938.5 2529,938.5 2518.4,938.5 2515,935.1 2515,924.9 2518.4,921.5 2529,921.5 2539.6,921.5 2543,918.1 2543,907.9 2539.6,904.5 2529,904.5 2524.45,904.5 2521.05,901.1 2521.05,890.9 2524.45,887.5 2529,887.5 2539.6,887.5 2543,884.1 2543,873.9 2539.6,870.5 2529,870.5 2523.83,870.5 2520.43,867.1 2520.43,856.9 2523.83,853.5 2529,853.5 2539.6,853.5 2543,850.1 2543,839.9 2539.6,836.5 2529,836.5 2518.4,836.5 2515,833.1 2515,822.9 2518.4,819.5 2529,819.5 2539.6,819.5 2543,816.1 2543,805.9 2539.6,802.5 2529,802.5 2526.38,802.5 2522.98,799.1 2522.98,788.9 2526.38,785.5 2529,782.88 2529,777 2529,714 2506.47,691.47 v1@2503.53,691.47
  Top Layer w15: v1(1328,666) 1328.76,666.76 U3.35@1328.76,709.38 ; U2.48@2458.36,691.47 2499.53,691.47 v1(2503.53,695.47)
  Signal Layer 3 w6: v1@1328,674 1328,861 1333,866 1805,866 1809,862 1809,563 1937,435 2003,435 2032,406 2068,406 2101,439 2173,439 2409,675 2443,675 2459.47,691.47 v1@2500.53,691.47
  Bottom Layer w6: v1@1994,1417 v1@1998,1421 ; v1(1994,1421) v1@1998,1421 ; J1.38@2415.88,1329.26 2415.88,1363.12 2317,1462 2039,1462 v1@1998,1421
EM_D13: J1.39@2400.13,1236.74 U2.50 U3.36 U4.41 | length 6522.4
  Top Layer w6: U4.41@498.42,1033.8 498.42,1004 498.42,1000.25 502.17,996.5 510.62,996.5 514.37,992.75 514.37,985.25 510.62,981.5 498.42,981.5 486.21,981.5 482.46,977.75 482.46,970.25 486.21,966.5 498.42,966.5 510.62,966.5 514.37,962.75 514.37,955.25 510.62,951.5 498.42,951.5 486.21,951.5 482.46,947.75 482.46,940.25 486.21,936.5 498.42,936.5 510.62,936.5 514.37,932.75 514.37,925.25 510.62,921.5 498.42,921.5 486.21,921.5 482.46,917.75 482.46,910.25 486.21,906.5 498.42,906.5 510.62,906.5 514.37,902.75 514.37,895.25 510.62,891.5 498.42,891.5 486.21,891.5 482.46,887.75 482.46,880.25 486.21,876.5 498.42,876.5 510.62,876.5 514.37,872.75 514.37,865.25 510.62,861.5 502.17,861.5 498.42,857.75 498.42,846.5 498.42,841.58 506,834 513.5,834 528.03,834 528.5,833.53 532.25,829.78 539.75,829.78 543.5,833.53 543.5,834 543.5,846.2 547.25,849.95 554.75,849.95 558.5,846.2 558.5,834 558.5,833.57 562.25,829.82 569.75,829.82 573.5,833.57 573.5,834 573.5,846.2 577.25,849.95 584.75,849.95 588.5,846.2 588.5,834 588.5,833.57 592.25,829.82 599.75,829.82 603.5,833.57 603.5,834 603.5,846.2 607.25,849.95 614.75,849.95 618.5,846.2 618.5,834 618.5,833.57 622.25,829.82 629.75,829.82 633.5,833.57 633.5,834 633.5,846.2 637.25,849.95 644.75,849.95 648.5,846.2 648.5,834 648.5,833.57 652.25,829.82 659.75,829.82 663.5,833.57 663.5,834 663.5,846.2 667.25,849.95 674.75,849.95 678.5,846.2 678.5,834 678.5,833.57 682.25,829.82 689.75,829.82 693.5,833.57 693.5,834 693.5,846.2 697.25,849.95 704.75,849.95 708.5,846.2 708.5,834 708.5,833.57 712.25,829.82 719.75,829.82 723.5,833.57 723.5,834 723.5,846.2 727.25,849.95 734.75,849.95 738.5,846.2 738.5,834 738.5,833.57 742.25,829.82 749.75,829.82 753.5,833.57 753.5,834 753.5,846.2 757.25,849.95 764.75,849.95 768.5,846.2 768.5,834 768.5,833.57 772.25,829.82 779.75,829.82 783.5,833.57 783.5,834 783.5,846.2 787.25,849.95 794.75,849.95 798.5,846.2 798.5,834 798.5,833.57 802.25,829.82 809.75,829.82 813.5,833.57 813.5,834 813.5,846.2 817.25,849.95 824.75,849.95 828.5,846.2 828.5,834 828.5,833.57 832.25,829.82 839.75,829.82 843.5,833.57 843.5,834 843.5,846.2 847.25,849.95 854.75,849.95 858.5,846.2 858.5,834 858.5,833.57 862.25,829.82 869.75,829.82 873.5,833.57 873.5,834 873.5,846.2 877.25,849.95 884.75,849.95 888.5,846.2 888.5,834 888.5,833.57 892.25,829.82 899.75,829.82 903.5,833.57 903.5,834 903.5,846.2 907.25,849.95 914.75,849.95 918.5,846.2 918.5,834 918.5,833.57 922.25,829.82 929.75,829.82 933.5,833.57 933.5,834 933.5,846.2 937.25,849.95 944.75,849.95 948.5,846.2 948.5,834 948.5,833.57 952.25,829.82 959.75,829.82 963.5,833.57 963.5,834 963.5,846.2 967.25,849.95 974.75,849.95 978.5,846.2 978.5,834 978.5,833.57 982.25,829.82 989.75,829.82 993.5,833.57 993.5,834 993.5,846.2 997.25,849.95 1004.75,849.95 1008.5,846.2 1008.5,834 1008.5,833.57 1012.25,829.82 1019.75,829.82 1023.5,833.57 1023.5,834 1023.5,846.2 1027.25,849.95 1034.75,849.95 1038.5,846.2 1038.5,834 1038.5,833.57 1042.25,829.82 1049.75,829.82 1053.5,833.57 1053.5,834 1053.5,846.2 1057.25,849.95 1064.75,849.95 1068.5,846.2 1068.5,834 1068.5,833.57 1072.25,829.82 1079.75,829.82 1083.5,833.57 1083.5,834 1083.5,846.2 1087.25,849.95 1094.75,849.95 1098.5,846.2 1098.5,837.75 1102.25,834 1213,834 v1@1297.26,749.74
  Top Layer w15: U3.36@1297.26,709.38 1297.26,749.74 v1(1297.26,752.74) ; U2.50@2458.36,754.46 v1@2500.54,754.46
  Signal Layer 3 w6: v1@1297,745 1297,876 1305,884 1313,884 1318.1,884 1321.5,887.4 1321.5,890.6 1324.9,894 1335.1,894 1338.5,890.6 1338.5,884 1338.5,882.4 1341.9,879 1352.1,879 1355.5,882.4 1355.5,884 1355.5,890.6 1358.9,894 1369.1,894 1372.5,890.6 1372.5,884 1372.5,882.4 1375.9,879 1386.1,879 1389.5,882.4 1389.5,884 1389.5,890.6 1392.9,894 1403.1,894 1406.5,890.6 1406.5,884 1406.5,882.4 1409.9,879 1420.1,879 1423.5,882.4 1423.5,884 1423.5,890.6 1426.9,894 1437.1,894 1440.5,890.6 1440.5,884 1440.5,882.4 1443.9,879 1454.1,879 1457.5,882.4 1457.5,884 1457.5,890.6 1460.9,894 1471.1,894 1474.5,890.6 1474.5,884 1474.5,882.4 1477.9,879 1488.1,879 1491.5,882.4 1491.5,884 1491.5,890.6 1494.9,894 1505.1,894 1508.5,890.6 1508.5,884 1508.5,882.4 1511.9,879 1522.1,879 1525.5,882.4 1525.5,884 1525.5,890.6 1528.9,894 1539.1,894 1542.5,890.6 1542.5,884 1542.5,882.4 1545.9,879 1556.1,879 1559.5,882.4 1559.5,884 1559.5,890.6 1562.9,894 1573.1,894 1576.5,890.6 1576.5,884 1576.5,882.4 1579.9,879 1590.1,879 1593.5,882.4 1593.5,884 1593.5,890.6 1596.9,894 1607.1,894 1610.5,890.6 1610.5,884 1610.5,882.4 1613.9,879 1624.1,879 1627.5,882.4 1627.5,884 1627.5,890.6 1630.9,894 1641.1,894 1644.5,890.6 1644.5,884 1644.5,882.4 1647.9,879 1658.1,879 1661.5,882.4 1661.5,884 1661.5,890.6 1664.9,894 1675.1,894 1678.5,890.6 1678.5,887.4 1681.9,884 1684,884 1692,884 1697.1,884 1700.5,887.4 1700.5,889.46 1703.9,892.86 1714.1,892.86 1717.5,889.46 1717.5,887.4 1720.9,884 1746,884 1818,884 1822,880 1822,570 1944,448 2009,448 2038,419 2058,419 2091,452 2167,452 2404,689 2433,689 2498.46,754.46 v1@2500.54,754.46
  Bottom Layer w6: J1.39@2400.13,1236.74 2400.13,1094 2400.13,1091 2404.63,1086.5 2420.63,1086.5 2425.13,1082 2425.13,1076 2420.63,1071.5 2400.13,1071.5 2379.63,1071.5 2375.13,1067 2375.13,1061 2379.63,1056.5 2400.13,1056.5 2420.63,1056.5 2425.13,1052 2425.13,1046 2420.63,1041.5 2400.13,1041.5 2379.63,1041.5 2375.13,1037 2375.13,1031 2379.63,1026.5 2400.13,1026.5 2420.63,1026.5 2425.13,1022 2425.13,1016 2420.63,1011.5 2400.13,1011.5 2379.63,1011.5 2375.13,1007 2375.13,1001 2379.63,996.5 2400.13,996.5 2420.63,996.5 2425.13,992 2425.13,986 2420.63,981.5 2400.13,981.5 2379.63,981.5 2375.13,977 2375.13,971 2379.63,966.5 2400.13,966.5 2420.63,966.5 2425.13,962 2425.13,956 2420.63,951.5 2404.63,951.5 2400.13,947 2400.13,938 2400.13,935.87 2411,925 2413.12,922.88 2419.49,922.88 2430.8,934.19 2437.16,934.19 2441.41,929.95 2441.41,923.59 2426.91,909.09 2412.78,894.96 2412.78,888.6 2417.03,884.36 2423.39,884.36 2434.33,895.3 2440.7,895.3 2443.5,892.5 2456,880 2456,872 2456,868.25 2459.75,864.5 2477.33,864.5 2481.08,860.75 2481.08,853.25 2477.33,849.5 2456,849.5 2436.6,849.5 2432.85,845.75 2432.85,838.25 2436.6,834.5 2456,834.5 2477.33,834.5 2481.08,830.75 2481.08,823.25 2477.33,819.5 2456,819.5 2445.67,819.5 2441.92,815.75 2441.92,808.25 2445.67,804.5 2456,804.5 2474.99,804.5 2478.74,800.75 2478.74,793.25 2474.99,789.5 2456,789.5 2434.67,789.5 2430.92,785.75 2430.92,778.25 2434.67,774.5 2456,774.5 2477.33,774.5 2481.08,770.75 2481.08,763.25 2477.33,759.5 2456,759.5 2434.67,759.5 2430.92,755.75 2430.92,748.25 2434.67,744.5 2452.25,744.5 2456,740.75 2456,732 2456,729 2428,701 2371,701 2365.9,701 2362.5,697.6 2362.5,678.4 2359.1,675 2348.9,675 2345.5,678.4 2345.5,701 2345.5,723.6 2342.1,727 2331.9,727 2328.5,723.6 2328.5,701 2328.5,678.4 2325.1,675 2314.9,675 2311.5,678.4 2311.5,701 2311.5,723.6 2308.1,727 2297.9,727 2294.5,723.6 2294.5,701 2294.5,678.4 2291.1,675 2280.9,675 2277.5,678.4 2277.5,701 2277.5,723.6 2274.1,727 2263.9,727 2260.5,723.6 2260.5,701 2260.5,678.4 2257.1,675 2246.9,675 2243.5,678.4 2243.5,697.6 2240.1,701 2230,701 2208,679 2208,649 2217,640 2224,640 2229.1,640 2232.5,643.4 2232.5,653.24 2235.9,656.64 2246.1,656.64 2249.5,653.24 2249.5,640 2249.5,626.76 2252.9,623.36 2263.1,623.36 2266.5,626.76 2266.5,640 2266.5,653.24 2269.9,656.64 2280.1,656.64 2283.5,653.24 2283.5,640 2283.5,626.76 2286.9,623.36 2297.1,623.36 2300.5,626.76 2300.5,640 2300.5,653.24 2303.9,656.64 2314.1,656.64 2317.5,653.24 2317.5,643.4 2320.9,640 2344,640 2354,640 2395,681 2455,681 2500.54,726.54 v1@2500.54,754.46
  other v1: 2502.54,754.46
